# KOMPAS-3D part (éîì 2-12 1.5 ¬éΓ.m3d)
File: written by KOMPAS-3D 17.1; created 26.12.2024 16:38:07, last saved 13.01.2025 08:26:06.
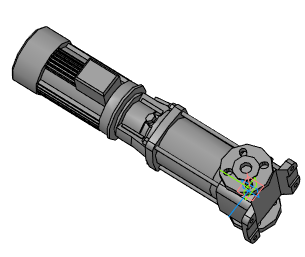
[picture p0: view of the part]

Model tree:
1. Операция без истории:4  (labels: ВМН 2-12 1.5 кВт)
